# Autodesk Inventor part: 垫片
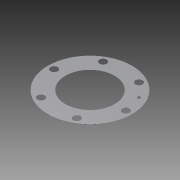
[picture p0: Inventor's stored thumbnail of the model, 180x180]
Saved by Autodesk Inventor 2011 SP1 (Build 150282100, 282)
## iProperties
Created: 2013-12
Part Number: 垫片
Document SubType Name: Modeling
Designer: Administrator
Density: 1 g/cm^3
Author: Administrator
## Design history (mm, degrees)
sketch "草图1"
  geometry: C1 r 24 at (0, 0); C2 r 41 at (0, 0); 1 further point
  constraints: 2 centre point, 2 coincident
  dimensions: "d0" = 48 diameter of C1; "d1" = 82 diameter of C2
extrude "拉伸1" new body sketch "草图1" distance "d2" = 0.1; taper "d3" = 0 deg
sketch "草图2"
  geometry: C1 r 24 at (0, 0) reference; 1 further point
  dimensions: "d4" = 35 distance of C1.centre point (-35, 0)
hole "Hole1" sketch "草图2" at (-35, 0) diameter "d5" = 7; stored, may be unused: countersink angle "d9" = 90 deg, drill point angle "d11" = 0 deg; dims "d6" = 6, "d7" = 4, "d8" = 2, "d10" = 8
pattern_circular "环形阵列1" dims angle "d13" = 360 deg
sketch "草图3"
  geometry: C1 r 1.5 at (30.311, 17.5)
  constraints: 1 centre point
  dimensions: "d17" = 3 diameter of C1
extrude "拉伸2" cut sketch "草图3" stored distance "d18" = 0.1; taper "d19" = 0 deg
node "实体1"
